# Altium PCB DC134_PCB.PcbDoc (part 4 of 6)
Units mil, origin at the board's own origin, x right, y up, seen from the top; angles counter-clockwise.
Board outline 4000 x 2750 mil, 6 copper layers (L1_Top Layer, L2_GND1, L3_Signal, L4_Plane, L5_GND2, L6_Bottom Layer), stack 57.7 mil thick; 399 components, 238 nets, 1523 pads, 671 vias.
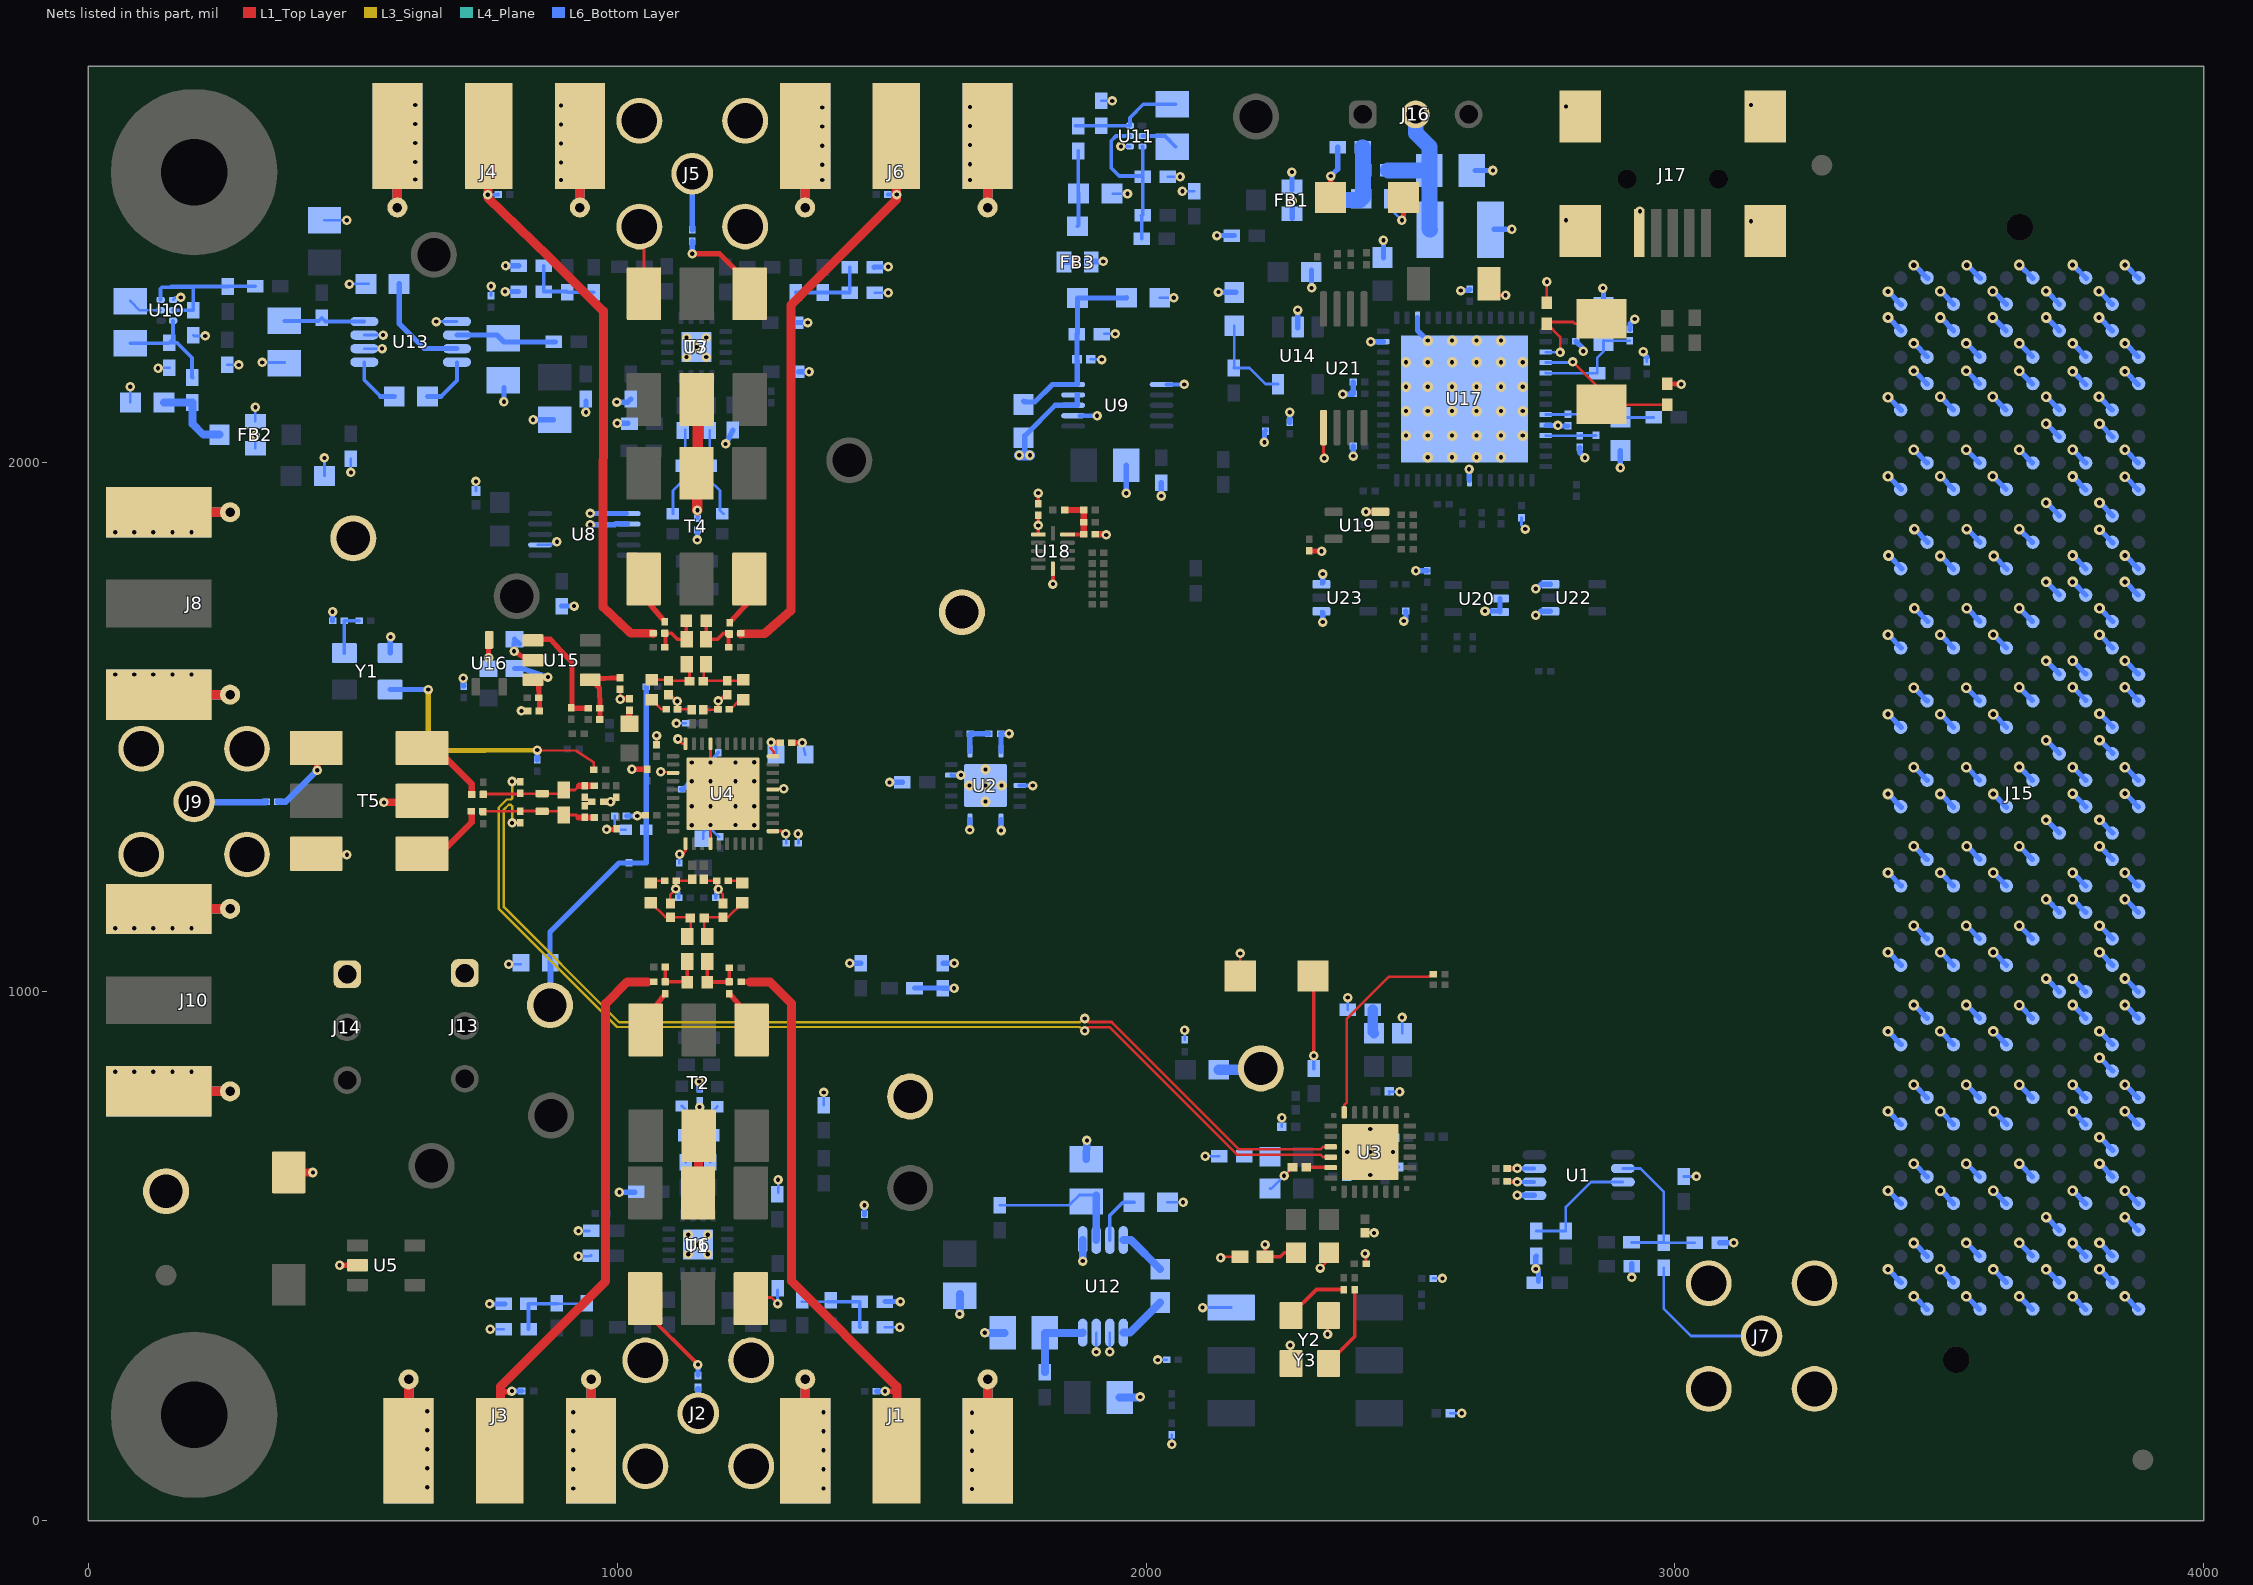
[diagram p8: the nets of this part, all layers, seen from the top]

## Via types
v1: diameter 18, hole 8, L1_Top Layer to L6_Bottom Layer, tented both sides, 429 vias
v2: diameter 20, hole 10, L1_Top Layer to L6_Bottom Layer, tented both sides, 183 vias
v3: diameter 19.68, hole 7.87, L1_Top Layer to L6_Bottom Layer, tented both sides, 37 vias
v4: diameter 19.68, hole 7.87, L1_Top Layer to L6_Bottom Layer, 17 vias
v5: diameter 18, hole 8, L1_Top Layer to L6_Bottom Layer, 5 vias

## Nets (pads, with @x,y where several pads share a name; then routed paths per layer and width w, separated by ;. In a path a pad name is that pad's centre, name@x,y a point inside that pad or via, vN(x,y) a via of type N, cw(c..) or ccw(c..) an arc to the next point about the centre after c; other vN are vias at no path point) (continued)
GND: C5.1 C7.1 C13.1 C15.1 C18.1 C19.1 C20.1 C22.1 C24.1 C27.2 C28.2 C29.2 C30.2 C31.2 C32.2 C33.2 C34.2 C35.2 C36.2 C37.2 C38.2 C39.2 C40.2 C41.2 C42.2 C43.2 C45.2 C46.2 C47.2 C48.2 C49.2 C50.1 C51.1 C54.2 C55.1 C56.1 C59.2 C60.2 C61.2 C62.2 C63.2 C64.2 C65.2 C66.2 C67.2 C68.2 C69.2 C70.2 C71.2 C72.2 C73.2 C74.2 C75.2 C76.2 C77.2 C78.2 C79.2 C80.2 C81.2 C82.2 C83.2 C84.2 C85.2 C86.2 C87.2 C90.2 C91.2 C92.2 C93.1 C94.2 C95.2 C96.2 C97.2 C98.2 C99.2 C100.2 C101.2 C102.2 C103.2 C104.2 C106.2 C107.2 C108.2 C109.2 C110.1 C111.1 C112.1 C113.2 C114.1 C115.1 C116.2 C117.1 C118.2 C119.1 C120.2 C121.2 C122.2 C123.2 C124.2 C125.1 C126.2 C127.2 C128.2 C129.2 D1.1 D2.1 FB1.2 FB2.2 FB3.2 J1.2 J1.3 J1.4 J1.5 J2.2 J2.3 J2.4 J2.5 J3.2 J3.3 J3.4 J3.5 J4.2 J4.3 J4.4 J4.5 J5.2 J5.3 J5.4 J5.5 J6.2 J6.3 J6.4 J6.5 J7.2 J7.3 J7.4 J7.5 J8.2 J8.3 J8.4 J8.5 J9.2 J9.3 J9.4 J9.5 J10.2 J10.3 J10.4 J10.5 J13.1 J14.1 J15.A1 J15.A4 J15.A5 J15.A8 J15.A9 J15.A12 J15.A13 J15.A16 J15.A17 J15.A20 J15.A21 J15.A24 J15.A25 J15.A28 J15.A29 J15.A32 J15.A33 J15.A36 J15.A37 J15.A40 J15.B2 J15.B3 J15.B6 J15.B7 J15.B10 J15.B11 J15.B14 J15.B15 J15.B18 J15.B19 J15.B22 J15.B23 J15.B26 J15.B27 J15.B30 J15.B31 J15.B34 J15.B35 J15.B38 J15.B39 J15.C1 J15.C4 J15.C5 J15.C8 J15.C9 J15.C12 J15.C13 J15.C16 J15.C17 J15.C20 J15.C21 J15.C24 J15.C25 J15.C28 J15.C29 J15.C32 J15.C33 J15.C36 J15.C38 J15.C40 J15.D2 J15.D3 J15.D6 J15.D7 J15.D10 J15.D13 J15.D16 J15.D19 J15.D22 J15.D25 J15.D28 J15.D37 J15.D39 J15.E1 J15.E4 J15.E5 J15.E8 J15.E11 J15.E14 J15.E17 J15.E20 J15.E23 J15.E26 J15.E29 J15.E32 J15.E35 J15.E38 J15.E40 J15.F2 J15.F3 J15.F6 J15.F9 J15.F12 J15.F15 J15.F18 J15.F21 J15.F24 J15.F27 J15.F30 J15.F33 J15.F36 J15.F39 J15.G1 J15.G4 J15.G5 J15.G8 J15.G11 J15.G14 J15.G17 J15.G20 J15.G23 J15.G26 J15.G29 J15.G32 J15.G35 J15.G38 J15.G40 J15.H2 J15.H3 J15.H6 J15.H9 J15.H12 J15.H15 J15.H18 J15.H21 J15.H24 J15.H27 J15.H30 J15.H33 J15.H36 J15.H39 J15.J1 J15.J4 J15.J5 J15.J8 J15.J11 J15.J14 J15.J17 J15.J20 J15.J23 J15.J26 J15.J29 J15.J32 J15.J35 J15.J38 J15.J40 J15.K2 J15.K3 J15.K6 J15.K9 J15.K12 J15.K15 J15.K18 J15.K21 J15.K24 J15.K27 J15.K30 J15.K33 J15.K36 J15.K39 J17.5 J17.6 J17.7 J17.8 J17.9 R33.1 R37.1 R42.1 R44.1 R52.1 R53.1 R57.1 R61.1 R65.1 R66.2 R67.1 R68.2 R69.1 R71.1 R72.1 R76.1 R79.2 R87.1 R92.2 R93.1 R96.2 R104.1 R109.2 R110.1 R121.1 R122.1 R127.1 R132.1 R152.1 S1.1 T1.3 T3.3 T5.3 T5.5 TP3.1 TP4.1 TP5.1 U1.5 U2.1 U2.5 U2.8 U2.11 U2.14 U2.15 U3.25 U4.3 U4.11 U4.14 U4.26 U4.37 U4.40 U4.41 U5.2 U6.17@1152.79,521.86 U7.17@1149.84,2219 U8.1 U8.2 U8.7 U9.1 U9.7 U10.4 U11.4 U12.2 U12.3 U12.5 U13.2 U13.3 U13.5 U14.2 U15.2 U16.3 U17.10 U17.21 U17.41 U17.45 U17.57 U18.6 U19.3 U20.2 U20.3 U21.5 U22.1 U22.3 U23.1 U23.3 Y1.2 Y2.2 Y2.4 Y3.3 | length 11218.2
  L1_Top Layer w5: T5.3@424,1259 v1(489,1259) ; R127.1@1005.4,1572 1006,1571.4 v1(1006,1553) ; J5.3@1042,2447 1050.64,2438.36 T3.3@1050.64,2320 ; C45.2@1074.5,1467.52 v1(1074.5,1484.5) ; v1(1082.5,1416) U4.3@1103.84,1414.07 ; U4.3@1103.54,1414.37 U4.3@1103.84,1414.07 ; U4.3@1103.91,1414 U4.3@1103.84,1414.07 ; U4.3@1105.63,1413.91 U4.3@1103.84,1414.07 ; v1(1115,1478) 1123.97,1469.03 U4.40@1129.25,1469.03 ; v1(1118.08,1260) 1123.13,1260 1129.25,1266.12 U4.11@1129.25,1280.06 ; U4.41@1160.66,1414 U4.41@1200.12,1374.54 U4.41@1208.45,1382.87 ; U4.14@1175.98,1278.17 1176,1280.06 U4.41@1176.37,1315.49 ; U4.41@1176.38,1434.06 U4.37@1176.38,1469.49 ; T1.3@1252.79,421.86 1291.96,421.86 v1(1303.32,410.5) ; U4.26@1292.22,1384 1290.64,1382.42 1294.59,1382.67 v1(1315,1384) ; U4.26@1294.36,1383 U4.26@1294.49,1382.87 ; v1(2141,497) 2143,499 C27.2@2177.88,499 ; D1.1@2178.1,1030 v1(2178.1,1072.48) ; v1(2261,651.99) R71.1@2277.01,668 ; Y2.2@2272.57,296.72 v1(2272.57,331.57) ; v1(2329.57,477.57) 2346.26,494.26 C28.2@2346.26,506.5 ; U21.5@2335.61,2066.8 2335.61,2019.41 2337,2018.03 v1(2337,2009) ; v1(2343.43,352.43) Y2.4@2343.43,387.28 ; v1(2414.16,505) 2416.02,501.98 R68.2@2416.02,486 ; C29.2@2414.16,544.01 v1(2431.2,544.01) ; v4(2424,697) U3.25@2433.84,687.16 ; C109.2@2648.93,2339 2670.93,2317 ; C109.2@2665.93,2316 v1@2675,2316 ; C123.2@2758,2302.69 v1(2758,2342.5) ; J17.5@2933.01,2416.64 J17.5@2934,2417.63
  L1_Top Layer w7: C121.2@1796.24,1924.02 v1(1796.24,1943) ; v1(1824,1771) U18.6@1824,1799.83
  L1_Top Layer w10: v1(475.15,482.85) U5.2@508.87,482.85 ; v1(756.78,1632) 756.78,1664.07 U16.3@758,1665.29 ; v1(805,1644) 828.52,1629 U15.2@850.71,1629 ; v1(819,1531) R132.1@830.98,1531 ; v1(980,1307) R52.1@999.87,1307 ; v1(1028,1421) C46.2@1057,1421.02 ; C37.2@1332.02,1471 v1(1350,1471) ; C126.2@2308.59,1833.98 2310.59,1833.98 v1(2332,1833) ; U21.5@2335.61,2066.8 U21.5@2337,2065.41 ; v1(2416,1907.59) U19.3@2443.29,1907.59 U19.3@2445.29,1907.59 ; v1(2484,2459) 2486.9,2461.9 D2.1@2486.9,2502 ; J17.5@2934,2417.63 v1(2934,2476) ; C124.2@2982,2150.5 2986.03,2150.3 v1(3012,2149)
  L1_Top Layer w12: v1(1006,1553) R76.1@1023.34,1553.85 ; C120.2@1906.02,1865 v1@1924,1865
  L1_Top Layer w15: S1.1@379,658.3 v1(424.7,658.3) ; v1(559,1358) T5.5@620,1359
  L4_Plane w5: v1(175,2313) v1@176.5,2313
  L6_Bottom Layer w5: C79.2@79.5,2114.5 v1(79.5,2144) ; v1(132,2179) 133.01,2180.01 C78.2@153.5,2180.01 ; U10.4@160.31,2308.32 164.99,2313 v1(175,2313) ; C76.2@198.5,2241.51 199.89,2240.12 v1(221.12,2240.12) ; R121.1@263,2185.38 v1(284.68,2185.38) ; FB2.2@316,2027.81 v1(316,2051.9) ; FB2.2@316,2078.99 v1(316,2105.4) ; v1(329,2189.97) C103.2@371.15,2189.97 ; C80.2@446.5,1975.5 v1(446.5,2009.5) ; C102.2@446.5,2459.06 v1(488.56,2459.06) ; v1@494.74,2339.11 C99.2@530.36,2339.11 ; v1(496.5,1982) C81.2@496.5,2007.88 ; U13.2@521.9,2216.2 v1(555.48,2216.2) ; U13.3@521.9,2241.8 v1(557.3,2241.8) ; Y1.2@567.81,1655.31 Y1.2@568.5,1656 ; J4.4@574,2704.62 577.38,2708 J4.4@603,2708 ; v1(658,2267.39) U13.5@697.1,2267.39 ; C82.2@733,1946.99 v1(733,1965) ; v1(759.87,361.74) R92.2@785.75,361.74 ; R110.1@761.5,2316.52 v1(761.5,2334) ; v1(795,1052) C48.2@817.13,1052 ; U8.7@850.34,1845.39 875,1845.39 880.68,1851.08 v1(886,1851.08) ; v1(926.87,499.75) C66.2@948.18,499.75 ; v1(926.87,547.74) C67.2@946.95,547.74 ; C66.2@950.63,501.74 C66.2@951.32,501.05 ; v1(980,1307) 994.5,1307 995.48,1307.98 ; C49.2@995.48,1332.5 995.48,1307.98 ; C47.2@1015.81,1306.29 997.16,1306.29 995.48,1307.98 ; v1(1112,1507.5) C13.1@1129.92,1507.5 ; C5.1@1117.28,1243.52 1117.28,1259.2 v1(1118.08,1260) ; C43.2@1163,1289.56 1163,1301.99 v4(1176.5,1315.49) ; v4@1179.73,1306.29 C41.2@1193,1293.02 ; v1(1303.32,410.5) C60.2@1303.32,436.12 ; C61.2@1304.32,620.33 v1(1304.32,644.74) ; C38.2@1343,1281 v1@1343,1298.02 ; v1(1350,1471) C39.2@1355.43,1448.56 ; R87.1@1390.87,785.33 v1(1390.87,809.74) ; R109.2@1487.12,2322 v1(1512.5,2322) ; R79.2@1506.37,365.74 v1(1534.37,365.74) ; C87.2@1895.49,2196 1916,2196 v1(1916.5,2195.5) ; v1(1905.98,319.02) U12.3@1905.98,355.4 ; C83.2@1915.15,2684.57 v1(1936,2684.57) ; C86.2@1921.38,2244 v1(1942,2244) ; v1(1931.57,319.45) U12.2@1931.57,355.4 ; C84.2@1937.43,2509 v1(1965,2509) ; v1(1952.68,2598.4) U11.4@1969.69,2598.4 ; v1@1988,233 v1(1989,234) ; v1(2022,304) R66.2@2038.98,304 ; C85.2@2026,2312.5 v1(2052.5,2312.5) ; C98.2@2040.5,602 v5(2070,602) ; C77.2@2041.13,2541.21 v1(2064.51,2541.21) ; v1(2049,144) R67.1@2049,161.98 ; v1(2068.99,2513.54) R122.1@2091.37,2513.54 ; C107.2@2073,909.02 v1(2073,927.15) ; v1(2107,403) Y3.3@2161.04,403 ; v1(2112,689) C31.2@2138.38,689 ; C32.2@2234.45,628 2237.01,628 v1(2261,651.99) ; R57.1@2257.01,745 v1(2257.01,762.01) ; C93.1@2272,2077.11 C93.1@2272.09,2077.02 ; U23.1@2331.71,1719.43 U23.1@2334,1717.14 ; U23.3@2331.71,1770.61 U23.3@2334.02,1772.93 ; C33.2@2379.49,650.15 2420.45,650.15 v4(2424,653.69) ; C34.2@2381.38,966 v1(2381.38,989) ; C112.1@2390.98,2130 C112.1@2391.98,2131 ; v1@2412.07,504.07 v1@2413,505 ; C36.2@2459.5,811.5 v1(2479.5,811) ; C36.2@2459.99,806.43 C36.2@2459.99,811.75 ; R72.1@2470.01,724 2470.01,699.7 v4(2467.31,697) 2452,681.69 R61.1@2452,670.99 2475.49,670.99 R69.1@2478.01,668.47 ; C73.2@2470,2499.5 2470,2473 v1(2484,2459) ; C35.2@2484.32,921.5 v1(2484.32,951.52) ; R65.1@2543.52,458 v1(2560.5,458) ; C30.2@2574.99,203 v1(2597,203) ; U20.3@2667.45,1719.98 U20.3@2669.4,1718.03 ; C111.1@2710,1896.57 2710,1882 v1(2717,1875) ; v1(2737,1712) v1@2738,1711 ; v1(2737,1762) v1@2738.41,1762 ; U17.10@2755.56,2071.79 U17.10@2756.35,2071 ; v1(2779,2071) v1@2780.02,2069.98 ; v1(2827,2211) v1@2827,2216.02 ; v1(2864,2330.61) v1@2865,2329.61 ; v1@2940.17,2206.83 v1(2940.17,2210.62) ; R152.1@2947,2191.02 2947,2200 ; v1(3040.77,650.77) C22.1@3017,650.77 3040.77,651 v1@3041,651
  L6_Bottom Layer w7: v4@1176.38,1434.06 1190.79,1452.14 1191,1452.4 C42.2@1191,1451.98 ; U2.5@1631.51,1409.88 U2.5@1631.51,1409.73 v1(1650,1409.73)
  L6_Bottom Layer w8: U2.11@1761.44,1390.04 1761.48,1390 v1(1786,1390) ; U9.7@1874.12,2089.31 v1(1907.5,2089.31) ; U9.1@2039.12,2148.37 v1(2072.5,2148.37)
  L6_Bottom Layer w10: R33.1@461.91,1701.52 v1(461.93,1718.52) ; Y1.2@570.81,1640.45 v1@570.81,1670.31 ; v1(709,1593) 709,1578.81 C104.2@709.78,1578.02 ; v1(758.87,409.74) C54.2@787.25,409.74 ; v1(786,2115.5) C96.2@786,2142.81 ; v1@791,2324 R96.2@812.76,2324 ; v1@792.12,2373 C55.1@813.88,2373 ; v1(805,1644) C108.2@805,1659.04 ; C108.2@806,1666.56 C108.2@815,1657.56 ; v1(841,2081.5) C97.2@879,2081.5 ; C75.2@895,1729.38 v1(918.62,1729.38) ; v1(941,2095.89) C62.2@941,2116.64 ; v1@949,1883 v1(949.08,1883) 993.45,1883 ; v1(949.08,1904.45) U8.1@1017.66,1904.45 ; 995.45,1883.24 997.21,1885 U8.2@1019.66,1885 ; v1(999.38,2115) 1020.13,2115 C63.2@1026.09,2120.96 ; v1(1000.28,2075) R104.1@1020.66,2075 ; v1(1004.32,620.74) C51.1@1033.7,620.74 ; C40.2@1122.02,1383 1125.32,1383 v4@1140.94,1398.62 ; v1(1151.5,1854.5) C15.1@1151.79,1873.2 ; C7.1@1155.37,813.26 v1(1155.37,830.11) v1@1155.37,832.74 ; v1@1206,2036.02 C56.1@1219,2062.38 ; C64.2@1336.62,2265.5 v1(1360.5,2265.5) ; C65.2@1343.62,2172.5 v1(1363,2172.5) ; v5(1439.62,1054.12) C69.2@1460.5,1054.12 ; R93.1@1467.63,578.15 v1(1467.63,596.26) ; C59.2@1485.62,2370.12 v1(1512.5,2371) ; C50.1@1506.32,414.24 v1(1535.69,414.24) ; v1(1515,1396) C18.1@1539.38,1396 ; C70.2@1616.62,1054 v5(1637.5,1054) ; v1(1666.94,1306) U2.1@1666.94,1325.08 ; v1(1726,1305) U2.14@1726,1325.08 ; U2.8@1726,1455 1726,1487.21 R53.1@1725.02,1488.19 v1(1741.19,1488.19) ; v1(1962.5,1942.5) C92.2@1962.5,1995.5 ; C68.2@2028.61,1962.38 v1(2029,1937.5) ; v1(2134,2430) C74.2@2162.38,2430 C74.2@2167.38,2430 ; v1(2137,2323) C91.2@2170.38,2323 ; v1(2224,2039) 2224,2058.89 C128.2@2226,2060.89 ; C93.1@2272,2077.11 v1(2272,2096) ; FB1.2@2276,2516.62 FB1.2@2276,2522.59 v1(2276,2550) ; FB1.2@2276.5,2462.62 v1(2276.5,2496) ; U14.2@2287,2255.62 v1(2287,2289) ; v1(2313,2331) C90.2@2313,2364.38 ; v1(2334,1699) U23.1@2334,1717.14 ; U23.3@2334,1772.95 v1(2334,1790) ; v1(2372,2130) C112.1@2390.98,2130 ; v1(2391.98,2013.05) C115.1@2391.98,2032 ; C112.1@2391.98,2131 C125.1@2391.98,2153.12 ; v1(2425,2229.27) U17.41@2448.47,2229.27 ; C113.2@2449.02,2387.62 v1(2449.02,2421) ; v1@2484.85,1701 v1(2487.17,1701) ; C129.2@2491.02,1720 2491.68,1719.29 v1@2491.68,1702 ; v1(2510.39,1796.02) C127.2@2532,1796.02 ; U17.45@2513.43,2274.54 2513.44,2250.65 v3(2532.75,2231.33) ; v1(2595,2326) 2609.98,2326 C110.1@2612,2328.02 ; v1(2611,1988) 2611,1968.32 U17.21@2611.86,1967.46 ; C72.2@2622.62,2553 v1(2656,2553) ; v1(2641,1720) U20.3@2667.43,1720 ; C71.2@2658.62,2441.91 v1(2692,2441.91) ; U20.3@2669.4,1718.03 U20.2@2669.4,1743.62 ; v1(2702,615.15) 2733.95,615.15 U1.5@2734.34,614.76 ; R42.1@2738,500.38 2737,499.38 v1(2737,476) 2742.38,470.62 C19.1@2742.38,452 ; v1@2738,1711 2746.41,1719.41 U22.1@2764.71,1719.41 ; v1@2738.41,1762 2747,1770.59 U22.3@2764.71,1770.59 ; U17.10@2756.35,2071 v1(2779,2071) ; v1@2780.02,2069.98 C117.1@2798,2069.98 ; C114.1@2813.02,2230 v1@2827,2216.02 ; C122.2@2820,2029.35 2820,2020 v1(2830,2010) ; C118.2@2865,2294.5 v1@2865,2329.61 ; v1(2897,1991) C116.2@2897,2023.5 ; C119.1@2915,2253.02 2915,2263 v1(2924,2272) ; v1(2918.62,460) C20.1@2918.62,481 C20.1@2918.62,486.38 ; v1@2940.17,2206.83 2947,2200 ; R37.1@3085,525.62 v1(3111.38,525.62) ; v2@3404,475 3427.59,450.57 J15.K39@3428,450.15 ; v2@3404,624 3427.09,600.09 J15.K36@3428,599.15 ; v2@3404,774 3427.09,750.09 J15.K33@3428,749.15 ; v2@3404,925 3427.59,900.57 J15.K30@3428,900.15 ; v2@3404,1075 3427.59,1050.57 J15.K27@3428,1050.15 ; v2@3404,1225.17 3427.67,1200.65 J15.K24@3428,1200.31 ; v2@3404,1374 3427.09,1350.09 J15.K21@3428,1349.15 ; v2@3404,1524.8 3427.49,1500.47 J15.K18@3428,1499.95 ; v2@3404,1675 3427.59,1650.57 J15.K15@3428,1650.15 ; v2@3404,1975 3427.59,1950.57 J15.K9@3428,1950.15 ; v2@3404,2124.34 3427.26,2100.25 J15.K6@3428,2099.49 ; v2@3404,2275 3427.59,2250.57 J15.K3@3428,2250.15 ; v2@3404,2324 3427.09,2300.09 J15.K2@3428,2299.15 ; v2@3405,1825 3428.11,1801.07 J15.K12@3429,1800.15 ; v2@3453,424 3476.57,399.59 J15.J40@3477,399.15 ; v2@3453,525 J15.J38@3477,500.15 ; v2@3453,675 J15.J35@3477,650.15 ; v2@3453,824 3476.57,799.59 J15.J32@3477,799.15 ; v2@3453,975.06 J15.J29@3477,950.21 ; v2@3453,1125 J15.J26@3477,1100.15 ; v2@3453,1274.98 J15.J23@3477,1250.13 ; v2@3453,1424.76 J15.J20@3477,1400 J15.J20@3477,1399.9 ; v2@3453,1575 J15.J17@3477,1550.15 ; v2@3453,2025 J15.J8@3477,2000.15 ; v2@3453,2174 3476.57,2149.59 J15.J5@3477,2149.15 ; v2@3453,2226 J15.J4@3477,2201.15 ; v2@3453,2374 J15.J1@3478,2349 ; v2@3454,1725 3477.59,1700.57 J15.J14@3478,1700.15 ; v2@3454,1875 3477.59,1850.57 J15.J11@3478,1850.15 ; v2@3503,475.15 J15.H39@3527,450.3 ; v2@3503,624 3526.57,599.59 J15.H36@3527,599.15 ; v2@3503,774 3526.57,749.59 J15.H33@3527,749.15 ; v2@3503,925.15 J15.H30@3527,900.3 ; v2@3503,1075 J15.H27@3527,1050.15 ; v2@3503,1225.17 J15.H24@3527,1200.31 ; v2@3503,1374 3526.57,1349.59 J15.H21@3527,1349.15 ; v2@3503,1525 J15.H18@3527,1500.15 ; v2@3503,1675 J15.H15@3527,1650.15 ; v2@3503,1824 3526.57,1799.59 J15.H12@3527,1799.15 ; v2@3503,1975 J15.H9@3527,1950.15 ; v2@3503,2125 J15.H6@3527,2100.15 ; v2@3503,2275 J15.H3@3527,2250.15 ; v2@3503,2324.85 J15.H2@3527,2300 ; v2@3552,424 J15.G40@3576,399.15 ; v2@3552,525.15 J15.G38@3576,500.3 ; v2@3552,675 J15.G35@3576,650.15 ; v2@3552,824 J15.G32@3576,799.15 ; v2@3552,975 J15.G29@3576,950.15 ; v2@3552,1125 J15.G26@3576,1100.15 ; v2@3552,1424.78 J15.G20@3576,1399.92 ; v2@3552,1575 J15.G17@3576,1550.15 ; v2@3552,2025 J15.G8@3576,2000.15 ; v2@3552,2174 J15.G5@3576,2149.15 ; v2@3552,2226 J15.G4@3576,2201.15 ; v2@3553,1274.98 J15.G23@3577,1250.13 ; v2@3553,1725 J15.G14@3577,1700.15 ; v2@3553,1875 J15.G11@3577,1850.15 ; v2@3553,2374 J15.G1@3578,2349 ; v2@3602,1975 J15.F9@3626,1950.15 ; v2@3602,2125 J15.F6@3626,2100.15 ; v2@3602,2275 J15.F3@3626,2250.15 ; v2@3602,2324.85 J15.F2@3627,2299.85 ; v2@3603,475 J15.F39@3627,450.15 ; v2@3603,624 3626.57,599.59 J15.F36@3627,599.15 ; v2@3603,925 J15.F30@3627,900.15 ; v2@3603,1075 J15.F27@3627,1050.15 ; v2@3603,1225 J15.F24@3627,1200.15 ; v2@3603,1374 3626.57,1349.59 J15.F21@3627,1349.15 ; v2@3603,1525 J15.F18@3627,1500.15 ; v2@3603,1675 J15.F15@3627,1650.15 ; v2@3604,774 3627.09,750.09 J15.F33@3628,749.15 ; v2@3604,1824 3627.09,1800.09 J15.F12@3628,1799.15 ; v2(3651,1875) J15.E11@3676,1850 ; v2@3652,424 J15.E40@3676,399.15 ; v2@3652,525.15 J15.E38@3676,500.3 ; v2@3652,675.15 J15.E35@3676,650.3 ; v2@3652,824 J15.E32@3676,799.15 ; v2@3652,974.8 J15.E29@3676,949.95 ; v2@3652,1125 J15.E26@3676,1100.15 ; v2@3652,1275.18 J15.E23@3676,1250.33 ; v2@3652,1425 J15.E20@3676,1400.15 ; v2@3652,1575.67 J15.E17@3676,1550.82 ; v2@3652,1725 J15.E14@3676,1700.15 ; v2@3652,2025 J15.E8@3676,2000.15 ; v2@3652,2174 J15.E5@3676,2149.15 ; v2@3652,2226 J15.E4@3676,2201.15 ; v2@3652,2374.22 J15.E1@3677,2349.22 ; v2@3703,475 J15.D39@3727,450.15 ; v2@3703,574 3726.57,549.59 J15.D37@3727,549.15 ; v2@3703,1025 J15.D28@3727,1000.15 ; v2@3703,1175.17 J15.D25@3727,1150.31 ; v2@3703,1325 J15.D22@3727,1300.15 ; v2@3703,1475.61 J15.D19@3727,1450.75 ; v2@3703,1625.67 J15.D16@3727,1600.82 ; v2@3703,1775 J15.D13@3727,1750.15 ; v2@3703,1925 J15.D10@3727,1900.15 ; v2@3703,2074.26 3726.7,2049.71 J15.D7@3727,2049.4 ; v2@3703,2125 J15.D6@3727,2100.15 ; v2@3703,2275 J15.D3@3727,2250.15 ; v2@3703,2325 J15.D2@3727,2300 ; v2@3753,424 3776.57,399.59 J15.C40@3777,399.15 ; v2@3753,525 J15.C38@3777,500.15 ; v2@3753,624 3776.57,599.59 J15.C36@3777,599.15 ; v2@3753,774 3776.57,749.59 J15.C33@3777,749.15 ; v2@3753,824 3776.57,799.59 J15.C32@3777,799.15 ; v2@3753,975 J15.C29@3777,950.15 ; v2@3753,1025 J15.C28@3777,1000.15 ; v2@3753,1175 J15.C25@3777,1150.15 ; v2@3753,1225 J15.C24@3777,1200.15 ; v2@3753,1374.76 J15.C21@3777,1350 J15.C21@3777,1349.9 ; v2@3753,1424.76 J15.C20@3777,1400 J15.C20@3777,1399.9 ; v2@3753,1576 J15.C17@3777,1551.15 ; v2@3753,1626 J15.C16@3777,1601.15 ; v2@3753,1775 J15.C13@3777,1750.15 ; v2@3753,1825 J15.C12@3777,1800.15 ; v2@3753,1974.42 3776.78,1949.79 J15.C9@3777,1949.57 ; v2@3753,2025 J15.C8@3777,2000.15 ; v2@3753,2173 3776.07,2149.11 J15.C5@3777,2148.15 ; v2@3753,2226 J15.C4@3777,2201.15 ; v2@3753,2374.22 J15.C1@3778,2349.22 ; v2@3803,2125 J15.B6@3827,2100.15 ; v2@3803,2275 J15.B3@3827,2250.15 ; v2@3803,2324.85 J15.B2@3827,2300 ; v2@3804,475.15 3827.67,450.64 J15.B39@3828,450.3 ; v2@3804,525.15 3827.67,500.64 J15.B38@3828,500.3 ; v2@3804,675.15 3827.67,650.64 J15.B35@3828,650.3 ; v2@3804,725.15 3827.67,700.64 J15.B34@3828,700.3 ; v2@3804,875.15 3827.67,850.64 J15.B31@3828,850.3 ; v2@3804,925.15 3827.67,900.64 J15.B30@3828,900.3 ; v2@3804,1075 3827.59,1050.57 J15.B27@3828,1050.15 ; v2@3804,1125 3827.59,1100.57 J15.B26@3828,1100.15 ; v2@3804,1275 3827.59,1250.57 J15.B23@3828,1250.15 ; v2@3804,1325 3827.59,1300.57 J15.B22@3828,1300.15 ; v2@3804,1476 J15.B19@3828,1451.15 ; v2@3804,1526 J15.B18@3828,1501.15 ; v2@3804,1675 3827.59,1650.57 J15.B15@3828,1650.15 ; v2@3804,1725 3827.59,1700.57 J15.B14@3828,1700.15 ; v2@3804,1874 3827.09,1850.09 J15.B11@3828,1849.15 ; v2@3804,1925 3827.59,1900.57 J15.B10@3828,1900.15 ; v2@3804,2074 3827.09,2050.09 J15.B7@3828,2049.15 ; v2@3852,424 J15.A40@3876,399.15 ; v2@3852,574 J15.A37@3876,549.15 ; v2@3852,624 J15.A36@3876,599.15 ; v2@3852,774 J15.A33@3876,749.15 ; v2@3852,824 J15.A32@3876,799.15 ; v2@3852,975.06 J15.A29@3876,950.21 ; v2@3852,1025.06 J15.A28@3876,1000.21 ; v2@3852,1175.17 J15.A25@3876,1150.31 ; v2@3852,1225.17 J15.A24@3876,1200.31 ; v2@3852,1374.78 J15.A21@3876,1349.92 ; v2@3852,1424.78 J15.A20@3876,1399.92 ; v2@3852,1576 J15.A17@3876,1551.15 ; v2@3852,1626 J15.A16@3876,1601.15 ; v2@3852,1775 J15.A13@3876,1750.15 ; v2@3852,1825 J15.A12@3876,1800.15 ; v2@3852,1974 J15.A9@3876,1949.15 ; v2@3852,2025 J15.A8@3876,2000.15 ; v2@3852,2173 3875.56,2148.61 J15.A5@3876,2148.15 ; v2@3852,2226 J15.A4@3876,2201.15 ; v2@3852,2374.22 J15.A1@3877,2349.22
  L6_Bottom Layer w12: FB3.2@1846.5,2380.65 v1@1868.45,2379.55 ; FB3.2@1897,2381.15 v1@1918.95,2380.05
  L6_Bottom Layer w15: v1@1648,391 C95.2@1648,428.37 ; v1@1695.4,355 C101.2@1732.78,355 ; v1(1880.39,490.89) U12.5@1880.39,530.6 ; C94.2@1887,683.5 v1@1888,718.5 ; C100.2@1950,233 v1@1988,233
  L6_Bottom Layer w18: 240,1906.75 J8.3@268,1906.75
  other v1: 1671,60 917,61 1390,61 641,63 1671,96 917,97 1390,97 641,99 1671,132 917,133 1390,133 641,135 1671,168 917,169 1390,169 641,171 1671,204 917,205 1390,205 641,207 1695,355.4 1647.6,390.6 1134.32,503.74 1171.32,503.74 1152.79,521.86 1134.32,540.74 1171.32,540.74 1888.4,718.9 51,849 87,849 123,849 159,849 195,849 51,1120 87,1120 123,1120 159,1120 195,1120 1342.02,1299 1141,1315 1259.17,1315 987.44,1359.3 1141,1433.6 1259.17,1433.9 51,1599.92 87,1599.92 123,1599.92 159,1599.92 195,1599.92 571.5,1671 1925,1864 51,1869 87,1869 123,1869 159,1869 195,1869 1205,2036.02 1131.32,2200.12 1168.32,2200.12 1149.85,2219 1131.32,2237.12 1168.32,2237.12 2680,2317 788,2324 493.86,2338.24 789.12,2373 1868.5,2380.5 1919,2381 3144,2457 2794,2459 894,2535 1388,2535 1667,2535 618,2536 1388,2564 1667,2565 894,2568 618,2569 1388,2600 1667,2601 894,2604 618,2605 1388,2636 1667,2637 894,2640 618,2641 1388,2672 1667,2673 2794,2674 894,2676 618,2677 3144,2677
  other v2: 3452,424 3551,424 3651,424 3752,424 3851,424 3403,475 3502,475.15 3602,475 3702,475 3803,475.15 3452,525 3551,525.15 3651,525.15 3752,525 3803,525.15 3702,574 3851,574 3403,624 3502,624 3602,624 3752,624 3851,624 3452,675 3551,675 3651,675.15 3803,675.15 3803,725.15 3403,774 3502,774 3603,774 3752,774 3851,774 3452,824 3551,824 3651,824 3752,824 3851,824 3803,875.15 3403,925 3502,925.15 3602,925 3803,925.15 3452,975.06 3551,975 3651,974.8 3752,975 3851,975.06 3702,1025 3752,1025 3851,1025.06 3403,1075 3502,1075 3602,1075 3803,1075 3452,1125 3551,1125 3651,1125 3803,1125 3702,1175.17 3752,1175 3851,1175.17 3403,1225.17 3502,1225.17 3602,1225 3752,1225 3851,1225.17 3452,1274.98 3552,1274.98 3651,1275.18 3803,1275 3702,1325 3803,1325 3403,1374 3502,1374 3602,1374 3752,1374.76 3851,1374.78 3452,1424.76 3551,1424.78 3651,1425 3752,1424.76 3851,1424.78 3702,1475.61 3803,1476 3403,1524.8 3502,1525 3602,1525 3803,1526 3452,1575 3551,1575 3651,1575.67 3752,1576 3851,1576 3702,1625.67 3752,1626 3851,1626 3403,1675 3502,1675 3602,1675 3803,1675 3453,1725 3552,1725 3651,1725 3803,1725 3702,1775 3752,1775 3851,1775 3502,1824 3603,1824 3404,1825 3752,1825 3851,1825 3803,1874 3453,1875 3552,1875 3702,1925 3803,1925 3752,1974.42 3851,1974 3403,1975 3502,1975 3601,1975 3452,2025 3551,2025 3651,2025 3752,2025 3851,2025 3702,2074.26 3803,2074 3403,2124.34 3502,2125 3601,2125 3702,2125 3802,2125 3752,2173 3851,2173 3452,2174 3551,2174 3651,2174 3452,2226 3551,2226 3651,2226 3752,2226 3851,2226 3403,2275 3502,2275 3601,2275 3702,2275 3802,2275 3403,2324 3502,2324.85 3601,2324.85 3702,2325 3802,2324.85 3452,2374 3552,2374 3651,2374.22 3752,2374.22 3851,2374.22
  other v3: 1696.48,1359.53 1665.96,1390.04 1696.48,1390.04 1726.99,1390.04 1696.48,1420.55 2532.75,2010.67 2578.93,2010.67 2625.11,2010.67 2671.29,2010.67 2491.68,2051.73 2532.75,2051.73 2578.93,2051.73 2625.11,2051.73 2671.29,2051.73 2712.35,2051.73 2491.68,2097.91 2532.75,2097.91 2578.93,2097.91 2625.11,2097.91 2671.29,2097.91 2712.35,2097.91 2491.68,2144.09 2532.75,2144.09 2578.93,2144.09 2625.11,2144.09 2671.29,2144.09 2712.35,2144.09 2491.68,2190.27 2532.75,2190.27 2578.93,2190.27 2625.11,2190.27 2671.29,2190.27 2712.35,2190.27 2578.93,2231.33 2625.11,2231.33 2671.29,2231.33
  other v4: 2380.69,697 2424,740.31 1223.74,1315.49 1141.06,1350.92 1176.5,1350.92 1223.74,1350.92 1259.17,1350.92 1141.06,1398.17 1176.5,1398.17 1223.74,1398.17 1259.17,1398.17 1176.5,1433.6 1223.74,1433.6
HW_SW_CTRL: R71.2 U3.23 | length 46.4
  L1_Top Layer w7: R71.2@2302.99,668 2348.67,668 U3.23@2349.2,667.47
InternalCLK_N: R51.1 U3.21 | length 2015.3
  L1_Top Layer w5: v1(801.38,1319.2) R51.1@817,1319.2 ; v1(1884,949.5) 1890.5,943 1935,943 2176,702 2330.04,702 2334.89,706.84 U3.21@2349.2,706.84
  L3_Signal w4.4: v1(801.38,1319.2) 801.38,1351.26 798.8,1353.84 795.16,1353.84 785.78,1344.46 785.78,1160.16 1003.37,942.57 1874.62,942.57 v1(1884,949.5) v1@1881.55,949.5
InternalCLK_P: R41.1 U3.22 | length 2044.1
  L1_Top Layer w5: v1(801.38,1397.62) R41.1@817,1397.62 ; v1(1884,926.5) 1890.5,933 1930.86,933 2171.86,692 2330.04,692 2334.89,687.16 U3.22@2349.2,687.16
  L3_Signal w4.4: 776.13,1276.52 776.13,1348.25 ; 776.38,1276.27 776.38,1156.62 999.58,933.43 1874.12,933.43 ; 776.63,1348.75 791.37,1363.49 798.8,1363.49 ; 799.5,1363.5 801.38,1365.56 v1(801.38,1397.62) ; 1874.62,932.93 v1@1883.32,926.5 ; v1@1881.55,926.5 v1@1883.32,926.5 ; v1@1884,926 1883.76,926.18 v1@1883.32,926.5 ; v1(1884,926.5) v1@1883.32,926.5
IOVDD: C37.1 C38.1 C39.1 C70.1 C121.1 L16.2 R114.1 TP7.1 U4.21 U4.30 U9.8 U9.9 U18.1 | length 410.8
  L1_Top Layer w5: v1(1291,1471.57) 1291,1459 1296,1454 1296,1447.38 U4.30@1294.49,1445.87 ; U4.21@1294.49,1304.13 1310,1304.13 1315.13,1299 v1(1319,1299)
  L1_Top Layer w7: v1@1796.02,1882.22 C121.1@1796.02,1900 ; U18.1@1796.44,1865.79 v1(1796.44,1881.8)
  L1_Top Layer w10: v1(1291,1471.57) C37.1@1303.4,1471.57
  L6_Bottom Layer w5: v1(1291,1471.57) 1300.32,1462.26 C39.1@1300.32,1448.56 ; v1(1319,1299) 1319.98,1298.02 C38.1@1319.98,1281
  L6_Bottom Layer w10: L16.2@1562.12,1007 1615.88,1007 C70.1@1616,1006.88 v5(1637.18,1006.88) ; 1770.5,2024.76 R114.1@1770.5,2052.07 ; R114.1@1771.57,2052.07 1828.5,2109 1869.84,2109 U9.9@1869.84,2128.68
  L6_Bottom Layer w20: v1(1760.19,2014.45) v1(1780.5,2014.45)
IOVDD+: C85.1 C86.1 C87.1 FB3.3 R114.2 U9.10 | length 370.7
  L6_Bottom Layer w10: R114.2@1768.44,2117.12 R114.2@1770.5,2115.06 ; R114.2@1771.5,2116.06 R114.2@1770.5,2115.06 ; C87.1@1869.51,2196 1869.51,2243.63 1870.5,2244.62 FB3.3@1870.5,2311.88 1962.38,2311.88 C85.1@1963,2312.5 ; C87.1@1869.84,2192.51 1869.84,2148.37 1822.87,2148.37 1789.56,2115.06 R114.2@1770.5,2115.06
NetC1_1: C1.1 J1.1 R2.2 | length 1079.1
  L1_Top Layer w10: C1.1@1234.29,1018.77 1251.51,1018.77 ; v1(1506.5,244.5) 1528.63,244.5
  L1_Top Layer w17: 1251.51,1018.77 1251.56,1018.72 1288.78,1018.72 1329.76,977.74 1329.76,452.74 1529,253.5 J1.1@1528.13,132
  L6_Bottom Layer w10: R2.2@1490.25,244.5 v1(1506.5,244.5)
NetC1_2: C1.2 C3.2 L2.2 R1.2 R3.1 | length 107.9
  L1_Top Layer w7: R3.1@1170.5,1057.38 1170.2,1057.08 L2.2@1170.2,1018.5 1211.97,1018.5 C3.2@1212.24,1018.77 ; C3.2@1212.24,1018.77 R1.2@1212.22,1045.5
NetC2_1: C2.1 J2.1 | length 46
  L6_Bottom Layer w12: J2.1@1153.37,203 C2.1@1153.37,249
NetC2_2: C2.2 T1.1 | length 191.1
  L1_Top Layer w7: T1.1@1055.5,417.15 T1.1@1052.79,419.86 1052.79,395 v1(1152.79,295)
  L6_Bottom Layer w10: C2.2@1152.87,276.02 1153.44,294.98 v1@1153.5,297
NetC3_1: C3.1 T2.1 | length 64.5
  L1_Top Layer w10: C3.1@1212.24,996.72 T2.1@1254.24,947.72
NetC4_1: C4.1 L1.1 R3.2 R4.1 | length 123.9
  L1_Top Layer w5: C4.1@1164.49,1139.5 1164.49,1110.63 R3.2@1170.5,1104.62 ; C4.1@1164.99,1133.29 1172.71,1141.01 R4.1@1200,1141.01 1209.71,1141.01 L1.1@1237,1168.3
NetC4_2: C4.2 L3.1 R10.2 R11.1 | length 118
  L1_Top Layer w5: L3.1@1063.79,1168.3 1091.08,1141.01 R11.1@1100.69,1141.01 1131.29,1141.01 1133.3,1139 1139.01,1133.29 R10.2@1139.01,1105
NetC6_1: C6.1 T2.3 | length 61.4
  L1_Top Layer w10: T2.3@1054.24,947.72 C6.1@1091.24,996.72
NetC6_2: C6.2 C8.2 L2.1 R10.1 R14.2 | length 109
  L1_Top Layer w7: R14.2@1090.96,1047 1090.96,1019.05 C6.2@1091.24,1018.77 1132.53,1018.77 L2.1@1132.8,1018.5 1132.8,1057.08 R10.1@1132.5,1057.38
NetC7_2: C7.2 T1.5 T2.5 | length 177
  L1_Top Layer w5: T2.5@1154.24,727.74 1155.87,729.37 v1(1155.87,782.11)
  L1_Top Layer w17: T1.5@1154.24,605.74 T2.5@1154.24,727.74
NetC8_1: C8.1 J3.1 R13.2 | length 1072
  L1_Top Layer w10: 779.25,243.5 v1@801.38,243.5 ; 1056.99,1018.72 C8.1@1063.89,1018.72
  L1_Top Layer w17: J3.1@778.13,132 779,253.5 978.24,452.74 978.24,977.74 1019.22,1018.72 1056.99,1018.72
  L6_Bottom Layer w10: v1(800.97,245) R13.2@819.97,245
NetC9_1: C9.1 J4.1 R16.2 | length 1150.7
  L1_Top Layer w17: J4.1@755,2653 755.12,2617.99 v1(755.5,2507) 755.5,2501.5 870.36,2390.17 973.76,2287 973.24,1728 1026,1678 C9.1@1068.04,1677.95
  L6_Bottom Layer w7: v1(755.5,2507) 774.22,2507 R16.2@774.72,2507.5
NetC9_2: C9.2 C11.2 L5.2 R15.2 R17.1 | length 108
  L1_Top Layer w7: R15.2@1090.09,1651.5 1091.6,1653.01 C11.2@1091.6,1677.95 ; C11.2@1090.09,1677.95 C11.2@1091.6,1677.95 ; L5.2@1130.8,1701.45 1130.8,1667.11 R17.1@1131.29,1666.62 1114.28,1666.62 1102.95,1677.95 C11.2@1091.6,1677.95
NetC10_1: C10.1 J5.1 | length 105.9
  L6_Bottom Layer w10: C10.1@1142,2441.1 J5.1@1142,2547
NetC10_2: C10.2 T3.1 | length 155.8
  L1_Top Layer w10: v1(1142,2395.5) 1193.64,2395.5 T3.1@1250.64,2338.5
  L6_Bottom Layer w10: v1(1142,2395.5) C10.2@1142,2419.06
NetC11_1: C11.1 T4.1 | length 49.7
  L1_Top Layer w10: T4.1@1058,1738 C11.1@1090.09,1700
NetC12_1: C12.1 L4.1 R17.2 R18.1 | length 101
  L1_Top Layer w5: L4.1@1065.55,1589.7 R18.1@1095.29,1589.7 ; R18.1@1101.29,1589.7 1103,1587.99 1135.91,1587.99 C12.1@1136.85,1587.05 1136.85,1613.82 R17.2@1131.29,1619.38
NetC12_2: C12.2 L6.1 R24.2 R25.1 | length 100.3
  L1_Top Layer w5: C12.2@1162.84,1587.05 1163.78,1587.99 1231.71,1587.99 L6.1@1233.42,1589.7 ; C12.2@1163.99,1591.39 R24.2@1163.99,1620
NetC14_1: C14.1 T4.3 | length 56.2
  L1_Top Layer w10: C14.1@1212.96,1698.82 1213.76,1698.86 T4.3@1251,1739.82
NetC14_2: C14.2 C16.2 L5.1 R24.1 R28.2 | length 107.8
  L1_Top Layer w7: L5.1@1168.2,1701.45 1168.2,1666.82 R24.1@1168,1666.62 1189.72,1666.62 1201.05,1677.95 C16.2@1211.37,1677.95 ; C16.2@1210.46,1675.98 1210.46,1652.41 R28.2@1211.37,1651.5
NetC15_2: C15.2 T3.5 T4.5 | length 207.8
  L1_Top Layer w20: v1(1151.79,1910.5) 1151.79,1974.55 1152,1974.76 T3.5@1152,2103
  L6_Bottom Layer w7: C15.2@1151.79,1895.25 v1(1151.79,1910.5)
NetC16_1: C16.1 J6.1 R27.2 | length 1165.8
  L1_Top Layer w5: 1425,2394 1425,2395
  L1_Top Layer w17: C16.1@1234.02,1676.98 1279,1677.24 1328.89,1721 1329,2299 1425,2395 1528.24,2498.24 J6.1@1528.24,2675
  L6_Bottom Layer w7: R27.2@1511.52,2507.5 v1(1528.5,2507.5)
NetC17_1: C17.1 R34.1 R37.2 U1.2 | length 311.8
  L6_Bottom Layer w5: U1.2@2901.66,665.95 2935.05,665.95 2979,622 C17.1@2979,525.62 ; R34.1@2918,526 2978.62,526 C17.1@2979,525.62 ; R37.2@3037.76,525.62 C17.1@2979,525.62
NetC17_2: C17.2 J7.1 | length 283.9
  L6_Bottom Layer w5: C17.2@2979,478.38 2979,401 3031,349 J7.1@3164,349
NetC21_1: C21.1 C25.1 L7.2 R41.2 R43.2 R45.1 R46.2 | length 219.1
  L1_Top Layer w5: R43.2@747,1373.98 747.09,1373.89 R41.2@820.24,1373.89 ; R41.2@817,1374.24 857.51,1374.24 L7.2@858,1374.73 892.11,1374.73 C25.1@899,1381.62 920.41,1381.62 928.46,1389.67
  L1_Top Layer w12: 928.46,1389.67 R45.1@938.44,1389.67 C21.1@956.42,1389.67
NetC23_1: C23.1 J9.1 | length 137.3
  L6_Bottom Layer w12: J9.1@200,1359.65 201,1358.65 335.96,1358.65 C23.1@336.61,1359.3
NetC23_2: C23.2 T5.1 | length 141.9
  L1_Top Layer w12: T5.1@431,1461 433,1459 v1(433,1419)
  L6_Bottom Layer w12: C23.2@358.66,1359.3 373.3,1359.3 v1(433,1419)
NetC24_2: C24.2 R45.2 R48.1
NetC25_2: C25.2 C26.1 L7.1 R47.2 R48.2 R49.2 R51.2 | length 217.7
  L1_Top Layer w5: R47.2@746.02,1341.27 746.17,1341.41 R51.2@819.24,1341.41 ; R51.2@817,1341.76 857.51,1341.76 L7.1@858,1341.27 892.11,1341.27 C25.2@899,1334.38 922.71,1334.38 927.46,1329.63
  L1_Top Layer w12: 927.46,1329.63 R48.2@938.44,1329.63 C26.1@956.42,1329.63
NetC27_1: C27.1 C31.1 C34.1 L8.1 L9.1 L10.1 R56.2 TP1.1 | length 201.1
  L1_Top Layer w7: v1(2225.12,522.12) C27.1@2225.12,499 2254,499 2261.5,506.5 L8.1@2283.89,506.5
  L6_Bottom Layer w19.68: R56.2@2137.5,852.62 TP1.1@2208,852.62 ; C34.1@2428.62,966 2428.62,924.08 L10.1@2431.2,921.5
NetC44_2: C44.2 R76.2 | length 22.4
  L1_Top Layer w12: C44.2@1023,1509.56 R76.2@1023,1531.98
NetC47_1: C47.1 C48.1 C49.1 R73.1 R74.1 R75.1 TP2.1 | length 742.6
  L6_Bottom Layer w7: v1(1038,1332.5) 1055,1332.5
  L6_Bottom Layer w10: C48.1@873.18,1055 873.18,1113.18 1003.39,1243.39 1053.14,1243.39 ; C49.1@1017.52,1332.5 v1(1038,1332.5) ; 1055,1243.39 1055,1332.5 R75.1@1054.98,1576.98
  L6_Bottom Layer w12: TP2.1@873.87,975.55 C48.1@873.87,1055
NetC50_2: C50.2 R79.1 R80.2 R81.2 | length 158.4
  L6_Bottom Layer w5: R81.2@1348.82,413.87 R80.2@1398.82,413.87
  L6_Bottom Layer w7: R80.2@1398.82,413.87 C50.2@1459,413.87 1459,365.87 R79.1@1459.13,365.74
NetC52_1: C52.1 L11.1 R82.2 | length 111.3
  L6_Bottom Layer w5: R82.2@1175.87,677.37 1175.87,769.48 L11.1@1189.43,783.04
NetC52_2: C52.2 L12.1 R88.2 | length 109.8
  L6_Bottom Layer w5: L12.1@1122.38,784.04 1129.87,776.55 R88.2@1129.87,677.37
NetC54_1: C54.1 R89.1 R90.1 R92.1 | length 160.3
  L6_Bottom Layer w5: R89.1@888.32,410.37 R90.1@944.32,410.37
  L6_Bottom Layer w7: R92.1@832.99,361.74 832.49,362.24 C54.1@832.49,410.37 R89.1@887.94,410.37
NetC55_2: C55.2 R96.1 R97.2 R98.2 | length 144.1
  L6_Bottom Layer w7: C55.2@861.12,2373 R96.1@861.12,2324 904.38,2324 R98.2@905.5,2322.88 R97.2@955.8,2322.88
NetC57_1: C57.1 L13.1 R99.2 | length 167.1
  L6_Bottom Layer w5: L13.1@1105.47,1903.7 1105.47,1947.47 1125.75,1967.75 C57.1@1125.75,1995 ; C57.1@1128.9,1995.22 R99.2@1128.9,2062.62
NetC57_2: C57.2 L14.1 R105.2 | length 169.1
  L6_Bottom Layer w5: C57.2@1172.99,1995 1172.99,1969.01 1194.53,1947.47 1194.53,1910.21 L14.1@1201.04,1903.7 ; C57.2@1174.9,1995.22 R105.2@1174.9,2061.38
NetC59_1: C59.1 R107.1 R108.1 R109.1 | length 150.7
  L6_Bottom Layer w7: R108.1@1337.5,2322.38 R107.1@1388.5,2322.38 1439.5,2322.38 R109.1@1439.88,2322 C59.1@1439.88,2370.12
NetC71_1: C71.1 C72.1 J16.2 L15.1 | length 307.6
  L6_Bottom Layer w30: L15.1@2457.79,2553.5 2458.29,2553 C72.1@2536,2553 ; J16.2@2510,2659 2510,2624 2536,2598 C72.1@2536,2553 ; C71.1@2536.91,2441 2536,2441.91 C72.1@2536,2553
NetC73_1: C73.1 FB1.1 L15.2 R113.2 | length 163.5
  L6_Bottom Layer w30: FB1.1@2343.91,2497 2404.5,2497 C73.1@2407,2499.5 2410.55,2503.04 L15.2@2410.55,2553.5 2410.55,2596.07 R113.2@2409.62,2597
NetC76_1: C76.1 R115.2 R119.2 U10.3 U10.5 | length 325.8
  L6_Bottom Layer w7: U10.3@136.69,2308.32 136.69,2329.19 139.5,2332 198.5,2332 ; 156.62,2333.62 R119.2@264,2333.62 264.38,2334 R115.2@315.38,2334 ; U10.5@160.31,2288.63 198.38,2288.63 C76.1@198.5,2288.76 198.5,2332 ; 199.62,2333.12 198.5,2332
NetC77_1: C77.1 R117.2 R120.2 U11.3 U11.5 | length 330.4
  L6_Bottom Layer w7: U11.5@1969.69,2618.09 1943.26,2618.09 1934.5,2609.32 1934.5,2557.59 1949.5,2542.59 1993.63,2542.59 1993.63,2598.08 U11.3@1993.31,2598.4 ; R117.2@1992.04,2423.91 1992.04,2466.56 1991.39,2467.21 1993.89,2469.71 C77.1@1993.89,2541.21
NetC78_1: C78.1 L17.2 R116.1 U10.6 | length 211
  L6_Bottom Layer w7: L17.2@79.5,2226.13 152.38,2226.13 C78.1@153.5,2227.26 ; U10.6@160.31,2268.95 160.31,2234.07 C78.1@153.5,2227.26 ; R116.1@197,2161.62 196,2162.62 196,2199 167.74,2227.26 C78.1@153.5,2227.26
NetC79_1: C79.1 FB2.1 R116.2 | length 154.1
  L6_Bottom Layer w15: C79.1@143,2114.5 196.88,2114.5 R116.2@197,2114.38 197,2073.89 217.49,2053.4 FB2.1@248.09,2053.4
NetC83_1: C83.1 L18.2 R118.1 U11.6 | length 221.2
  L6_Bottom Layer w7: R118.1@1866.18,2637.47 1920.27,2637.47 C83.1@1920.56,2637.76 ; C83.1@1914.97,2637.32 1915.42,2637.77 U11.6@1969.69,2637.77 1969.69,2652.78 1995,2678.09 L18.2@2049.5,2678.09 L18.2@2056,2678.09
NetC84_1: C84.1 FB3.1 R118.2 | length 143.2
  L6_Bottom Layer w7: FB3.1@1870.5,2447.7 1872.45,2449.65 C84.1@1872.45,2509.56 1872,2510 R118.2@1872,2589.88
NetC88_1: C88.1 U12.1 | length 93.3
  L6_Bottom Layer w15: U12.1@1957.16,355.4 1969.67,355.4 C88.1@2026.78,412.5
NetC88_2: C88.2 U12.8 | length 92.4
  L6_Bottom Layer w15: U12.8@1957.16,530.6 1971.67,530.6 C88.2@2026.78,475.5
NetC89_1: C89.1 U13.1 | length 103.2
  L6_Bottom Layer w7: U13.1@521.9,2190.61 521.9,2156.94 553.12,2125.72
  L6_Bottom Layer w10: 553.12,2125.72 C89.1@578.5,2125.72
NetC89_2: C89.2 U13.8 | length 102.9
  L6_Bottom Layer w7: 667,2125.72 697.1,2155.82 U13.8@697.1,2190.61
  L6_Bottom Layer w10: C89.2@641.5,2125.72 667,2125.72
NetC91_1: C91.1 L19.1 U14.5 | length 176.6
  L6_Bottom Layer w5: C91.1@2167,2259.5 2167,2180.62 L19.1@2166,2179.62 2195.52,2179.62 2226,2149.15 2249.32,2149.15 U14.5@2249.6,2148.87
NetC94_1: C94.1 R123.1 U12.6 | length 275.1
  L6_Bottom Layer w5: R123.1@1723.5,596.62 1854.86,596.62 1873.99,615.75 1905.21,615.75 C94.1@1905.98,614.98
  L6_Bottom Layer w15: U12.6@1905.98,530.6 C94.1@1905.98,614.98
NetC96_1: C96.1 R124.1 U13.6 | length 191.4
  L6_Bottom Layer w10: U13.6@697.1,2241.8 772.7,2241.8 785.88,2228.62 R124.1@883,2228.62
NetC98_1: C98.1 U12.7 | length 102.6
  L6_Bottom Layer w7: U12.7@1931.57,530.6 1931.57,576.83 1956.74,602 C98.1@1977.5,602
NetC99_1: C99.1 U13.7 | length 203.9
  L6_Bottom Layer w10: C99.1@587.79,2338.61 587.79,2263.71 635.3,2216.2 U13.7@697.1,2216.2
NetC101_1: C101.1 R125.2 U12.4 | length 146.2
  L6_Bottom Layer w15: R125.2@1808.78,280.62 C101.1@1808.78,355 1879.99,355 U12.4@1880.39,355.4
NetC103_1: C103.1 R126.2 U13.4 | length 156.7
  L6_Bottom Layer w7: C103.1@370.5,2268.5 435.62,2268.5 R126.2@441.5,2274.38 448.49,2267.39 U13.4@521.9,2267.39
NetC105_1: C105.1 R129.1 U15.1 | length 210.5
  L1_Top Layer w10: U15.1@840.87,1666.4 873.57,1666.4 893.5,1644.5 914.5,1623.5 914.5,1536 C105.1@945.48,1536
NetC105_2: C105.2 R127.2 R128.1 U15.4 | length 127.5
  L1_Top Layer w10: U15.4@949.13,1591.6 R127.2@1005.4,1594.05 ; U15.4@958.29,1582.71 966.52,1574.48 C105.2@967.52,1536 R128.1@967.52,1514.95
NetC108_1: C108.1 R131.2 R132.2 U15.3 | length 145.5
  L1_Top Layer w10: U15.3@840.87,1591.6 v1(869,1595) ; U15.3@852,1582 R131.2@852.02,1556.02 853.02,1555.02 R132.2@853.02,1531
  L6_Bottom Layer w10: C108.1@806,1611.44 820.56,1611.44 v1(869,1595)
NetC116_1: C116.1 C117.2 L20.2 U17.9 | length 207.5
  L6_Bottom Layer w5: U17.9@2755.56,2091.47 2797.45,2091.47 C117.2@2798,2092.02 2870,2092.02 2875.53,2086.5 C116.1@2897,2086.5 2897.5,2086 L20.2@2960.38,2086
NetC118_1: C118.1 C119.2 L21.2 U17.5 | length 215.1
  L6_Bottom Layer w5: U17.5@2755.56,2170.21 2756.27,2169.5 L21.2@2853.38,2169.5 2853.38,2199 2865,2210.62 C118.1@2865,2231.5 2865.53,2230.98 C119.2@2915,2230.98
NetC120_1: C120.1 R147.2 R150.2 R151.2 U18.11 | length 112.5
  L1_Top Layer w5: C120.1@1881.76,1864.79 C120.1@1881.98,1865
  L1_Top Layer w7: U18.11@1851.56,1864.79 C120.1@1881.76,1864.79
  L1_Top Layer w12: R147.2@1846.02,1911 R150.2@1881.98,1911 R151.2@1881.98,1888 C120.1@1881.98,1865
NetC122_1: C122.1 R153.2 U17.11 | length 96
  L6_Bottom Layer w5: U17.11@2755.56,2052.1 2756.26,2051.4 C122.1@2820,2051.4 2820.62,2052.02 R153.2@2851,2052.02
NetC123_1: C123.1 U17.3 Y4.1 | length 201.9
  L1_Top Layer w5: v1(2783,2209) 2783,2238.31 C123.1@2758,2263.31 2761.18,2266.5 2807.83,2266.5 2811.02,2263.31 2851.61,2263.31 Y4.1@2861,2272.71
  L6_Bottom Layer w5: U17.3@2755.56,2209.58 2756.14,2209 v1(2783,2209)
NetC124_1: C124.1 U17.4 Y4.2 | length 279.4
  L1_Top Layer w5: v1(2807,2191) 2861.98,2136.02 2861.98,2110.31 C124.1@2986,2110.31
  L6_Bottom Layer w5: U17.4@2755.56,2189.9 2805.9,2189.9 v1(2807,2191)
NetD1_2: D1.2 R58.1 | length 175.5
  L1_Top Layer w7: D1.2@2315.9,1030 2317,1028.9 v1(2317,879)
  L6_Bottom Layer w7: R58.1@2317,855 v1(2317,879)
NetD2_2: D2.2 R113.1 | length 100.5
  L1_Top Layer w10: D2.2@2349.1,2502 2349.5,2502.4 v1(2349.5,2542.5)
  L6_Bottom Layer w10: v1(2349.5,2542.5) 2362.38,2555.38 R113.1@2362.38,2597
NetL1_2: L1.2 R6.1 | length 28.8
  L1_Top Layer w5: R6.1@1210.02,1210 1232.7,1210 L1.2@1237,1205.7
NetL3_2: L3.2 R9.1 | length 28
  L1_Top Layer w5: L3.2@1063.79,1205.7 1068.09,1210 R9.1@1089.98,1210
NetL4_2: L4.2 R20.1 | length 39
  L1_Top Layer w5: L4.2@1065.55,1552.3 1083.85,1534 R20.1@1096.98,1534
NetL6_2: L6.2 R23.1 | length 33
  L1_Top Layer w5: R23.1@1208.02,1534 1214,1534 1232.3,1552.3 L6.2@1233.42,1552.3
NetL17_1: L17.1 U10.2 | length 64.4
  L6_Bottom Layer w5: L17.1@79.5,2306.13 97,2288.63 U10.2@136.69,2288.63
NetL18_1: L18.1 U11.2 | length 71
  L6_Bottom Layer w7: U11.2@1993.31,2618.09 2036,2618.09 L18.1@2056,2598.09
NetR4_2: R4.2 R5.1 R6.2 R7.2 | length 91.5
  L1_Top Layer w5: R5.1@1163.85,1213.01 1166.86,1210 R6.2@1187.98,1210 1187.98,1196.02 1200,1184 R4.2@1200,1166.99
  L6_Bottom Layer w7: R7.2@1186.22,1178.08 1186.22,1188.72 v1(1191.5,1194)
NetR8_1: R8.1 R9.2 R11.2 R12.1 | length 97.6
  L1_Top Layer w5: R11.2@1100.69,1166.99 1100.69,1183.67 1112.02,1195 R9.2@1112.02,1210 1138.99,1210 R12.1@1142,1213.01
  L6_Bottom Layer w7: v1(1111,1194.5) 1116.48,1189.02 R8.1@1116.48,1178.08
NetR18_2: R18.2 R19.1 R20.2 R21.2 | length 68.5
  L1_Top Layer w5: R18.2@1103,1562.01 1103,1560.02 v1(1113.5,1549.52) R20.2@1114.52,1534 ; R20.2@1119.02,1534 1139.99,1534 R19.1@1141,1532.99
  L6_Bottom Layer w5: R21.2@1113.78,1534 v1@1113.78,1547.72
NetR22_1: R22.1 R23.2 R25.2 R26.1 | length 68.2
  L1_Top Layer w5: R26.1@1163,1532.99 R23.2@1183.97,1532.99 ; R23.2@1189.98,1534 v1(1191,1550) 1203,1561 R25.2@1203,1562.01
  L6_Bottom Layer w5: R22.1@1191.07,1534.5 v1@1191.07,1548.43
NetR29_1: R29.1 R30.1 Y1.3 | length 533
  L1_Top Layer w5: v1(849,1457) 923,1456 925,1454 955.98,1433.9 R30.1@955.98,1420
  L3_Signal w10: v1(643,1571.55) 643,1467 654,1456 v1(849,1457)
  L6_Bottom Layer w10: Y1.3@570.81,1571.55 v1(643,1571.55) ; v1(849,1457) 849.15,1456.85 R29.1@849.15,1439.02
NetR31_1: R31.1 R33.2 Y1.1 | length 89.2
  L6_Bottom Layer w7: Y1.1@484.19,1640.45 483.95,1640.69 R33.2@483.95,1701.52 R31.1@511.95,1701.52
NetR32_1: R32.1 R35.1 U1.7 | length 70.3
  L1_Top Layer w7: R32.1@2683.02,666 v1(2702,666)
  L6_Bottom Layer w7: R35.1@2683.02,666 v1(2702,666) 2734.28,666 U1.7@2734.34,665.95
NetR36_1: R36.1 R38.1 U1.6 | length 71.7
  L1_Top Layer w7: R38.1@2683.02,642 2684.67,640.35 v1(2702,640.35)
  L6_Bottom Layer w7: R36.1@2683.02,642 2700.35,642 v1(2702,640.35) U1.6@2734.34,640.35
NetR40_1: R40.1 R42.2 U1.3 | length 228.7
  L6_Bottom Layer w5: R42.2@2738,547.62 R40.1@2794,547.62 2794,593 2841.35,640.35 U1.3@2901.66,640.35
NetR46_1: R46.1 T5.6 | length 128.1
  L1_Top Layer w5: T5.6@643,1457.3 T5.6@660.66,1457.3
  L1_Top Layer w12: T5.6@660.66,1457.3 724.98,1392.99 R46.1@724.98,1373.54
NetR47_1: R47.1 T5.4 | length 128.5
  L1_Top Layer w5: T5.4@643,1257.3 T5.4@661.39,1257.3
  L1_Top Layer w12: T5.4@661.39,1257.3 724.98,1320.89 R47.1@724.98,1341.06
NetR50_1: R50.1 R53.2 U2.7 | length 68.5
  L6_Bottom Layer w10: U2.7@1666.94,1455 1666.94,1486.92 R50.1@1668.02,1488 1702.79,1488 R53.2@1702.98,1488.19
NetR55_2: R55.2 Y2.1 | length 122
  L1_Top Layer w7: Y2.1@2272.57,387.28 2322.27,436.98 R55.2@2374,436.98
NetR59_2: R59.2 Y2.3 | length 161.4
  L1_Top Layer w7: Y2.3@2343.43,296.72 2394.47,347.76 R59.2@2394.47,436.98
NetR60_1: R60.1 U3.18 | length 372.7
  L1_Top Layer w5: U3.18@2374.79,771.8 2374.79,786.11 2379.63,790.96 2379.63,949.14 2459,1028 ; 2459,1028.5 2534,1028.5 R60.1@2538.84,1032.84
